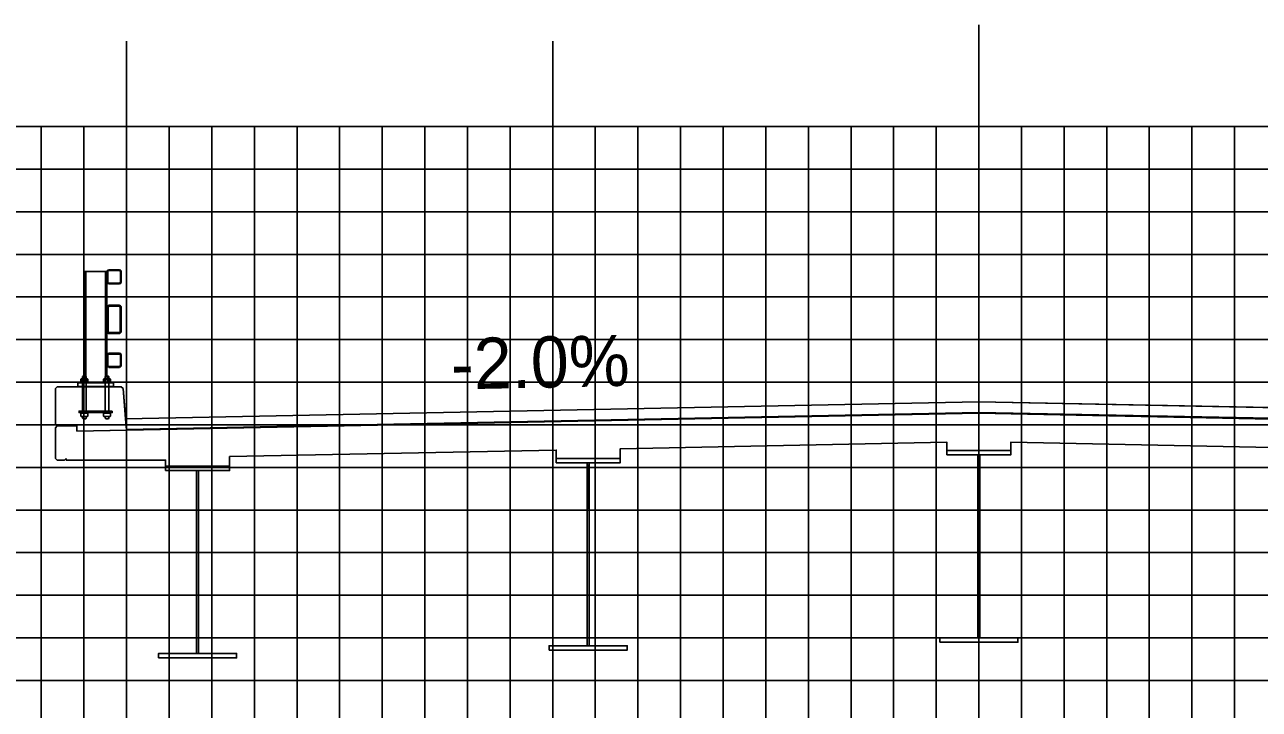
# Model space of a CAD drawing. Extents: x 1790124 to 1790467, y 442591 to 442811.
# Drawn here: x 1790267.31 to 1790296.28, y 442704.99 to 442721.06 of the extents above; entities that cross this region are included whole.
import ezdxf

# ---------------------------------------------------------------- set-up
doc = ezdxf.new("R2010")
doc.units = 0
for name, color, linetype in [('ANNOTATION', 7, 'Continuous'), ('BORDER', 7, 'Continuous'), ('D_Bridge_Framing', 7, 'Continuous'), ('D_Bridge_Railing', 7, 'Continuous'), ('D_Bridge_Superstructure', 7, 'Continuous'), ('DIMENSIONS', 7, 'Continuous'), ('MAJOR', 7, 'Continuous'), ('MINOR', 7, 'Continuous'), ('PATTERNING', 7, 'Continuous'), ('SHADING', 7, 'Continuous')]:
    doc.layers.add(name, color=color, linetype=linetype)

msp = doc.modelspace()

# ---------------------------------------------------------------- linework, layer by layer
at = {"layer": 'BORDER'}
for p, q in [((1790280.529, 442710.732), (1790280.529, 442709.695)), ((1790289.696, 442710.837), (1790289.696, 442709.799))]:
    msp.add_line(p, q, dxfattribs=at)
at = {"layer": 'D_Bridge_Framing'}
for points in [[(1790288.946, 442710.957), (1790290.446, 442710.957), (1790290.446, 442711.062), (1790288.946, 442711.062)], [(1790279.779, 442710.774), (1790281.279, 442710.774), (1790281.279, 442710.878), (1790279.779, 442710.878)], [(1790280.506, 442710.774), (1790280.553, 442710.774), (1790280.553, 442706.482), (1790280.506, 442706.482)], [(1790289.672, 442710.957), (1790289.719, 442710.957), (1790289.719, 442706.666), (1790289.672, 442706.666)], [(1790270.612, 442710.591), (1790272.112, 442710.591), (1790272.112, 442710.695), (1790270.612, 442710.695)], [(1790271.339, 442710.591), (1790271.386, 442710.591), (1790271.386, 442706.299), (1790271.339, 442706.299)], [(1790288.779, 442706.562), (1790290.612, 442706.562), (1790290.612, 442706.666), (1790288.779, 442706.666)], [(1790279.612, 442706.378), (1790281.446, 442706.378), (1790281.446, 442706.482), (1790279.612, 442706.482)], [(1790270.446, 442706.195), (1790272.279, 442706.195), (1790272.279, 442706.299), (1790270.446, 442706.299)]]:
    msp.add_lwpolyline(points, close=True, dxfattribs=at)
at = {"layer": 'D_Bridge_Railing'}
for p, q in [((1790268.706, 442715.264), (1790268.706, 442712.807)), ((1790268.706, 442715.264), (1790269.237, 442715.264)), ((1790268.743, 442715.264), (1790268.743, 442712.802)), ((1790269.201, 442715.264), (1790269.201, 442712.802)), ((1790269.237, 442715.014), (1790269.237, 442715.264)), ((1790269.237, 442715.264), (1790269.237, 442712.807)), ((1790269.258, 442715.014), (1790269.258, 442715.264)), ((1790269.279, 442715.306), (1790269.529, 442715.306)), ((1790269.279, 442715.285), (1790269.529, 442715.285)), ((1790269.55, 442715.264), (1790269.55, 442715.014)), ((1790269.571, 442715.264), (1790269.571, 442715.014)), ((1790269.529, 442714.993), (1790269.279, 442714.993)), ((1790269.529, 442714.972), (1790269.279, 442714.972)), ((1790269.289, 442714.472), (1790269.519, 442714.472)), ((1790269.237, 442713.858), (1790269.237, 442714.421)), ((1790269.263, 442713.858), (1790269.263, 442714.421)), ((1790269.289, 442714.446), (1790269.519, 442714.446)), ((1790269.545, 442714.421), (1790269.545, 442713.858)), ((1790269.571, 442714.421), (1790269.571, 442713.858)), ((1790269.519, 442713.832), (1790269.289, 442713.832)), ((1790269.519, 442713.806), (1790269.289, 442713.806)), ((1790269.237, 442713.056), (1790269.237, 442713.306)), ((1790269.258, 442713.056), (1790269.258, 442713.306)), ((1790269.279, 442713.347), (1790269.529, 442713.347)), ((1790269.279, 442713.327), (1790269.529, 442713.327)), ((1790269.55, 442713.306), (1790269.55, 442713.056)), ((1790269.571, 442713.306), (1790269.571, 442713.056)), ((1790269.529, 442713.035), (1790269.279, 442713.035)), ((1790269.529, 442713.014), (1790269.279, 442713.014)), ((1790268.665, 442712.797), (1790268.748, 442712.797)), ((1790268.665, 442712.735), (1790268.665, 442712.672)), ((1790268.706, 442712.807), (1790268.706, 442712.65)), ((1790268.747, 442712.735), (1790268.747, 442712.672)), ((1790269.279, 442712.797), (1790269.196, 442712.797)), ((1790269.196, 442712.735), (1790269.196, 442712.672)), ((1790269.238, 442712.807), (1790269.238, 442712.65)), ((1790269.279, 442712.735), (1790269.279, 442712.672)), ((1790268.665, 442712.556), (1790268.665, 442712.65)), ((1790268.748, 442712.556), (1790268.748, 442712.65)), ((1790269.196, 442712.556), (1790269.196, 442712.65)), ((1790269.279, 442712.556), (1790269.279, 442712.65)), ((1790268.665, 442711.986), (1790268.665, 442711.954)), ((1790268.748, 442711.986), (1790268.748, 442711.954)), ((1790269.196, 442711.986), (1790269.196, 442711.954)), ((1790269.279, 442711.986), (1790269.279, 442711.954))]:
    msp.add_line(p, q, dxfattribs=at)
for points in [[(1790268.624, 442712.735), (1790268.64, 442712.745), (1790268.772, 442712.745), (1790268.788, 442712.735), (1790268.788, 442712.672), (1790268.772, 442712.663), (1790268.64, 442712.663), (1790268.624, 442712.672)], [(1790269.32, 442712.735), (1790269.303, 442712.745), (1790269.171, 442712.745), (1790269.155, 442712.735), (1790269.155, 442712.672), (1790269.171, 442712.663), (1790269.303, 442712.663), (1790269.32, 442712.672)], [(1790268.555, 442712.65), (1790269.388, 442712.65), (1790269.388, 442712.566), (1790268.555, 442712.566)], [(1790268.555, 442712.566), (1790269.388, 442712.566), (1790269.388, 442712.556), (1790268.555, 442712.556)], [(1790268.619, 442712.65), (1790268.793, 442712.65), (1790268.793, 442712.663), (1790268.619, 442712.663)], [(1790269.324, 442712.65), (1790269.151, 442712.65), (1790269.151, 442712.663), (1790269.324, 442712.663)], [(1790269.362, 442711.986), (1790268.581, 442711.986), (1790268.581, 442711.954), (1790269.362, 442711.954)]]:
    msp.add_lwpolyline(points, close=True, dxfattribs=at)
for points in [[(1790268.665, 442712.745), (1790268.665, 442712.797), (1790268.675, 442712.807), (1790268.737, 442712.807), (1790268.748, 442712.797), (1790268.748, 442712.745)], [(1790269.279, 442712.745), (1790269.279, 442712.797), (1790269.269, 442712.807), (1790269.206, 442712.807), (1790269.196, 442712.797), (1790269.196, 442712.745)], [(1790268.665, 442712.556), (1790268.665, 442711.986)], [(1790268.748, 442712.556), (1790268.748, 442711.986)], [(1790269.196, 442712.556), (1790269.196, 442711.986)], [(1790269.279, 442712.556), (1790269.279, 442711.986)], [(1790268.793, 442711.954), (1790268.793, 442711.941), (1790268.619, 442711.941), (1790268.619, 442711.954)], [(1790268.64, 442711.941), (1790268.624, 442711.932), (1790268.624, 442711.869), (1790268.64, 442711.859), (1790268.772, 442711.859), (1790268.788, 442711.869), (1790268.788, 442711.932), (1790268.772, 442711.941)], [(1790268.665, 442711.859), (1790268.665, 442711.818), (1790268.675, 442711.807), (1790268.737, 442711.807), (1790268.748, 442711.818), (1790268.748, 442711.859)], [(1790269.151, 442711.954), (1790269.151, 442711.941), (1790269.324, 442711.941), (1790269.324, 442711.954)], [(1790269.303, 442711.941), (1790269.32, 442711.932), (1790269.32, 442711.869), (1790269.303, 442711.859), (1790269.171, 442711.859), (1790269.155, 442711.869), (1790269.155, 442711.932), (1790269.171, 442711.941)], [(1790269.279, 442711.859), (1790269.279, 442711.818), (1790269.269, 442711.807), (1790269.206, 442711.807), (1790269.196, 442711.818), (1790269.196, 442711.859)]]:
    msp.add_lwpolyline(points, dxfattribs=at)
for centre, radius, start, end in [((1790269.279, 442715.264), 0.0415, 90, 180), ((1790269.279, 442715.264), 0.0206, 90, 180), ((1790269.529, 442715.264), 0.0415, 0, 90), ((1790269.529, 442715.264), 0.0206, 0, 90), ((1790269.279, 442715.014), 0.0415, 180, 270), ((1790269.279, 442715.014), 0.0206, 180, 270), ((1790269.529, 442715.014), 0.0415, 270, 0), ((1790269.529, 442715.014), 0.0206, 270, 0), ((1790269.289, 442714.421), 0.0518, 90, 180), ((1790269.519, 442714.421), 0.0518, 360, 90), ((1790269.289, 442714.421), 0.0257, 90, 180), ((1790269.519, 442714.421), 0.0257, 360, 90), ((1790269.289, 442713.858), 0.0518, 180, 270), ((1790269.289, 442713.858), 0.0257, 180, 270), ((1790269.519, 442713.858), 0.0518, 270, 0), ((1790269.519, 442713.858), 0.0257, 270, 0), ((1790269.279, 442713.306), 0.0415, 90, 180), ((1790269.279, 442713.306), 0.0206, 90, 180), ((1790269.529, 442713.306), 0.0415, 0, 90), ((1790269.529, 442713.306), 0.0206, 0, 90), ((1790269.279, 442713.056), 0.0415, 180, 270), ((1790269.279, 442713.056), 0.0206, 180, 270), ((1790269.529, 442713.056), 0.0415, 270, 0), ((1790269.529, 442713.056), 0.0206, 270, 0), ((1790268.645, 442712.706), 0.036, 55.4339, 120), ((1790268.706, 442712.606), 0.136, 72.412, 107.588), ((1790268.768, 442712.706), 0.036, 60, 124.5661), ((1790269.176, 442712.706), 0.036, 55.4339, 120), ((1790269.237, 442712.606), 0.136, 72.412, 107.588), ((1790269.299, 442712.706), 0.036, 60, 124.5661), ((1790268.645, 442712.702), 0.036, 240, 304.5661), ((1790268.706, 442712.802), 0.136, 252.412, 287.588), ((1790268.768, 442712.702), 0.036, 235.4339, 300), ((1790269.176, 442712.702), 0.036, 240, 304.5661), ((1790269.237, 442712.802), 0.136, 252.412, 287.588), ((1790269.299, 442712.702), 0.036, 235.4339, 300)]:
    msp.add_arc(centre, radius, start, end, dxfattribs=at)
at = {"layer": 'D_Bridge_Superstructure'}
for p, q in [((1790268.029, 442712.514), (1790268.071, 442712.556)), ((1790268.029, 442712.514), (1790268.029, 442711.68)), ((1790269.571, 442712.556), (1790268.071, 442712.556)), ((1790269.616, 442712.514), (1790269.571, 442712.556)), ((1790269.616, 442712.514), (1790269.696, 442711.537)), ((1790289.696, 442712.207), (1790269.674, 442711.807)), ((1790289.696, 442712.207), (1790309.718, 442711.807)), ((1790289.696, 442711.937), (1790268.529, 442711.513)), ((1790289.696, 442711.957), (1790269.694, 442711.557)), ((1790289.696, 442711.957), (1790309.697, 442711.557)), ((1790289.696, 442711.937), (1790310.862, 442711.513)), ((1790309.696, 442711.537), (1790289.696, 442711.937)), ((1790268.071, 442711.638), (1790268.029, 442711.68)), ((1790268.529, 442711.638), (1790268.071, 442711.638)), ((1790268.529, 442711.638), (1790268.071, 442711.638)), ((1790268.529, 442711.638), (1790268.529, 442711.513)), ((1790268.529, 442711.513), (1790268.529, 442711.638)), ((1790288.946, 442711.062), (1790290.446, 442711.062)), ((1790268.237, 442710.837), (1790268.279, 442710.878)), ((1790268.279, 442710.878), (1790268.279, 442710.837)), ((1790279.779, 442710.878), (1790281.279, 442710.878)), ((1790270.612, 442710.695), (1790272.112, 442710.695))]:
    msp.add_line(p, q, dxfattribs=at)
for points in [[(1790289.696, 442711.937), (1790269.696, 442711.537), (1790268.529, 442711.513)], [(1790268.071, 442711.638), (1790268.029, 442711.597), (1790268.029, 442710.878), (1790268.071, 442710.837), (1790268.237, 442710.837)], [(1790268.071, 442711.638), (1790268.029, 442711.597), (1790268.029, 442710.878), (1790268.071, 442710.837), (1790268.237, 442710.837)], [(1790272.112, 442710.695), (1790272.112, 442710.918), (1790279.779, 442711.072), (1790279.779, 442710.878)], [(1790281.279, 442710.878), (1790281.279, 442711.102), (1790288.946, 442711.255), (1790288.946, 442711.062)], [(1790290.446, 442711.062), (1790290.446, 442711.255), (1790298.112, 442711.102), (1790298.112, 442710.878)], [(1790268.279, 442710.878), (1790268.237, 442710.837)], [(1790268.279, 442710.878), (1790268.279, 442710.837)], [(1790268.279, 442710.837), (1790270.612, 442710.837), (1790270.612, 442710.695)]]:
    msp.add_lwpolyline(points, dxfattribs=at)
at = {"layer": 'DIMENSIONS'}
msp.add_line((1790289.696, 442721.056), (1790289.696, 442705.843), dxfattribs=at)
at = {"layer": 'MAJOR'}
for p, q in [((1790269.696, 442720.669), (1790269.696, 442718.665)), ((1790279.696, 442720.669), (1790279.696, 442718.665)), ((1790289.696, 442720.669), (1790289.696, 442718.665)), ((1790149.696, 442718.665), (1790429.696, 442718.665)), ((1790149.696, 442718.665), (1790429.696, 442718.665)), ((1790269.696, 442673.665), (1790269.696, 442718.665)), ((1790279.696, 442673.665), (1790279.696, 442718.665)), ((1790289.696, 442673.665), (1790289.696, 442718.665)), ((1790149.696, 442713.665), (1790429.696, 442713.665)), ((1790149.696, 442708.665), (1790429.696, 442708.665))]:
    msp.add_line(p, q, dxfattribs=at)
at = {"layer": 'MINOR'}
for p, q in [((1790267.696, 442673.665), (1790267.696, 442718.665)), ((1790268.696, 442673.665), (1790268.696, 442718.665)), ((1790270.696, 442673.665), (1790270.696, 442718.665)), ((1790271.696, 442673.665), (1790271.696, 442718.665)), ((1790272.696, 442673.665), (1790272.696, 442718.665)), ((1790273.696, 442673.665), (1790273.696, 442718.665)), ((1790274.696, 442673.665), (1790274.696, 442718.665)), ((1790275.696, 442673.665), (1790275.696, 442718.665)), ((1790276.696, 442673.665), (1790276.696, 442718.665)), ((1790277.696, 442673.665), (1790277.696, 442718.665)), ((1790278.696, 442673.665), (1790278.696, 442718.665)), ((1790280.696, 442673.665), (1790280.696, 442718.665)), ((1790281.696, 442673.665), (1790281.696, 442718.665)), ((1790282.696, 442673.665), (1790282.696, 442718.665)), ((1790283.696, 442673.665), (1790283.696, 442718.665)), ((1790284.696, 442673.665), (1790284.696, 442718.665)), ((1790285.696, 442673.665), (1790285.696, 442718.665)), ((1790286.696, 442673.665), (1790286.696, 442718.665)), ((1790287.696, 442673.665), (1790287.696, 442718.665)), ((1790288.696, 442673.665), (1790288.696, 442718.665)), ((1790290.696, 442673.665), (1790290.696, 442718.665)), ((1790291.696, 442673.665), (1790291.696, 442718.665)), ((1790292.696, 442673.665), (1790292.696, 442718.665)), ((1790293.696, 442673.665), (1790293.696, 442718.665)), ((1790294.696, 442673.665), (1790294.696, 442718.665)), ((1790295.696, 442673.665), (1790295.696, 442718.665)), ((1790149.696, 442717.665), (1790429.696, 442717.665)), ((1790149.696, 442716.665), (1790429.696, 442716.665)), ((1790149.696, 442715.665), (1790429.696, 442715.665)), ((1790149.696, 442714.665), (1790429.696, 442714.665)), ((1790149.696, 442712.665), (1790429.696, 442712.665)), ((1790149.696, 442711.665), (1790429.696, 442711.665)), ((1790149.696, 442710.665), (1790429.696, 442710.665)), ((1790149.696, 442709.665), (1790429.696, 442709.665)), ((1790149.696, 442707.665), (1790429.696, 442707.665)), ((1790149.696, 442706.665), (1790429.696, 442706.665)), ((1790149.696, 442705.665), (1790429.696, 442705.665))]:
    msp.add_line(p, q, dxfattribs=at)
at = {"layer": 'PATTERNING'}
for p, q in [((1790268.071, 442712.556), (1790268.029, 442712.514)), ((1790268.029, 442712.514), (1790268.029, 442711.68)), ((1790269.571, 442712.556), (1790268.071, 442712.556)), ((1790269.616, 442712.514), (1790269.571, 442712.556)), ((1790269.674, 442711.807), (1790269.616, 442712.514)), ((1790268.029, 442711.68), (1790268.071, 442711.638)), ((1790268.071, 442711.638), (1790268.529, 442711.638)), ((1790268.529, 442711.638), (1790268.529, 442711.513)), ((1790268.529, 442711.513), (1790269.696, 442711.537))]:
    msp.add_line(p, q, dxfattribs=at)
msp.add_lwpolyline([(1790269.696, 442711.537), (1790269.694, 442711.557), (1790269.674, 442711.807)], dxfattribs=at)
at = {"layer": 'SHADING'}
for p, q in [((1790289.696, 442712.207), (1790269.674, 442711.807)), ((1790289.696, 442712.207), (1790269.674, 442711.807)), ((1790269.694, 442711.557), (1790289.696, 442711.957)), ((1790269.694, 442711.557), (1790289.696, 442711.957)), ((1790289.696, 442711.957), (1790309.697, 442711.557)), ((1790289.696, 442711.957), (1790309.697, 442711.557)), ((1790269.674, 442711.807), (1790269.694, 442711.557)), ((1790269.674, 442711.807), (1790269.694, 442711.557))]:
    msp.add_line(p, q, dxfattribs=at)
msp.add_lwpolyline([(1790309.718, 442711.807), (1790292.825, 442712.145), (1790289.696, 442712.207)], dxfattribs=at)
msp.add_lwpolyline([(1790309.718, 442711.807), (1790292.825, 442712.145), (1790289.696, 442712.207)], dxfattribs=at)

# ---------------------------------------------------------------- texts
at = {"layer": 'ANNOTATION'}
msp.add_text('-2.0%', height=1.2, rotation=1.1458, dxfattribs=at).set_placement((1790277.32, 442712.494))

doc.saveas('drawing.dxf')
